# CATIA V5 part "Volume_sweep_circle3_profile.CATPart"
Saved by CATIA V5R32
Part number: Part1
Bounding box of the stored display mesh (mm): x -210.021 to 26.553, y 0 to 145.736, z -54.983 to 55
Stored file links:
  D:\PROJECTS\Project 2022\CATIA V5 6R 2022\Resources\Part Files\c17_catia_v6_6r2022_prt\Volume_sweep_circle3_profile.CATPart
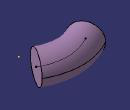
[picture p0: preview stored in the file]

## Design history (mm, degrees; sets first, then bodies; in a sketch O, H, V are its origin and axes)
Set1
  Sketch1 on xy-plane, origin (0, 0, 0), H (1, 0, 0), V (0, 1, 0)
    line L1 (0, 0) -> (-183.1008, 0)
    horizontal: L1 H
  Sketch2 on xy-plane, origin (0, 0, 0), H (1, 0, 0), V (0, 1, 0)
    spline S1 through (0, 65.5148) (-89.6654, 90.7245) (-183.6013, 65.5148)
    point P1 (0, 65.5148)
    coincidence: P1 V
  Sweep1: type Circle, Guide Sketch2, Radius 55
Body1 (main body)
